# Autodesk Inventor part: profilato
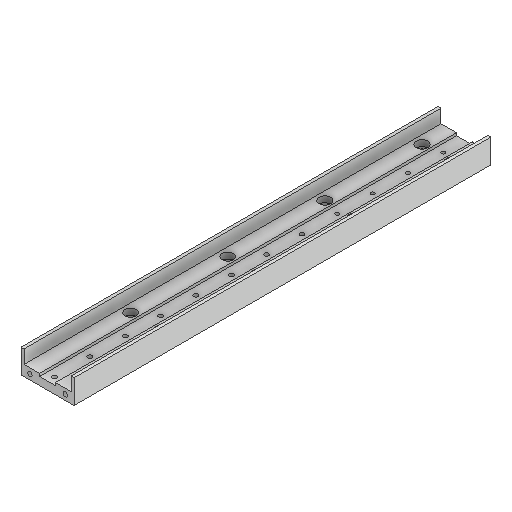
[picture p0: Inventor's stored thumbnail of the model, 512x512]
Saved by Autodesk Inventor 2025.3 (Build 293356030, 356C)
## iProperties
Created: 2025-11
Part Number: profilato
Material: Generico
Document SubType Name: Modeling
Designer: R5800u
Density: 1 g/cm^3
Appearance: Default
Author: R5800u
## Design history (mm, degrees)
feature "Base1"
sketch "Schizzo1"
  geometry: L1 (30, 0)-(30, -5.7) reference; L2 (30, 0)-(19.5, 0) reference; L3 (19.5, -1.2)-(19.5, 0) reference; L4 (10.5, -1.2)-(19.5, -1.2) reference; L5 (10.5, 0)-(10.5, -1.2) reference; L6 (0, 0)-(10.5, 0) reference; L7 (0, -5.7)-(0, 0) reference; L8 (30, -5.7)-(0, -5.7) reference; C1 r 1.45 at (5, -2.7) reference; C2 r 1.45 at (25, -2.7) reference; 1 further point
extrude "Estrusione1" cut sketch "Schizzo1" distance "d0" = 10; taper "d1" = 0 deg
sketch "Schizzo2"
  geometry: L1 (9.75, 2.6)-(3.25, 2.6) reference; L2 (0, 5.7)-(10.5, 5.7) reference; L3 (0, 5.7)-(0, 0) reference; L4 (0, 0)-(30, 0) reference; L5 (30, 0)-(30, 5.7) reference; L6 (19.5, 5.7)-(30, 5.7) reference; L7 (19.5, 5.7)-(19.5, 4.5) reference; L8 (19.5, 4.5)-(10.5, 4.5) reference; L9 (10.5, 4.5)-(10.5, 5.7) reference; C1 r 1.45 at (5, 3) reference; C2 r 1.45 at (25, 3) reference; 1 further point
extrude "Estrusione2" cut sketch "Schizzo2" stored distance "d2" = 10; taper "d3" = 0 deg
sketch "Schizzo3"
  geometry: L1 (19.5, 6)-(28.3, 6) reference; L2 (19.5, 4.5)-(19.5, 6) reference; L3 (10.5, 4.5)-(19.5, 4.5) reference; L4 (10.5, 6)-(10.5, 4.5) reference; L5 (1.7, 6)-(10.5, 6) reference; L6 (1.7, 13.6)-(1.7, 6) reference; L7 (1.7, 13.6)-(0, 13.6) reference; L8 (0, 0)-(0, 13.6) reference; L9 (30, 0)-(0, 0) reference; L10 (30, 0)-(30, 13.6) reference; L11 (30, 13.6)-(28.3, 13.6) reference; L12 (28.3, 6)-(28.3, 13.6) reference; C1 r 1.45 at (5, 3) reference; C2 r 1.45 at (25, 3) reference; 1 further point
extrude "Estrusione3" join sketch "Schizzo3" distance "d4" = 150; taper "d5" = 0 deg
sketch "Schizzo4"
  geometry: L1 (-4.5, -72)-(-4.5, -127); L2 (4, -70.5)-(4, -125.5); L3 (-13, -70.5)-(-13, -125.5); C1 r 1.7 at (4, -70.5) reference; C2 r 1.025 at (-4.5, -72) reference; C3 r 1.7 at (-13, -70.5) reference; C4 r 1.7 at (4, -15.5) reference; 4 further points
  constraints: 6 end point, 3 coincident, 3 vertical
  dimensions: "d6" = 55 distance of L2.start C4.centre (derived); "d7" = 55 distance of L1.start L1.end; "d8" = 55 distance of L2.start L2.end
hole "Foro1" sketch "Schizzo4" diameter "d9" = 2.4; stored, may be unused: countersink angle "d13" = 90 deg, drill point angle "d15" = 118 deg; dims "d10" = 6, "d11" = 4.4, "d12" = 2, "d14" = 8
hole "Foro2" sketch "Schizzo4" diameter "d16" = 3.242; stored, may be unused: countersink angle "d20" = 90 deg, drill point angle "d22" = 118 deg; dims "d17" = 8, "d18" = 6.3, "d19" = 3.4, "d21" = 8
pattern_linear "Serie rettangolare1" dims "d25" = 55
pattern_linear "Serie rettangolare2"
sketch "Schizzo5"
  geometry: C1 r 1.45 at (5, 3) reference; C2 r 1.45 at (25, 3) reference; 1 further point
hole "Foro3" sketch "Schizzo5" at (5, 3), (25, 3) diameter "d29" = 2.459; stored, may be unused: countersink angle "d33" = 90 deg, drill point angle "d35" = 118 deg; dims "d30" = 6, "d31" = 19.05, "d32" = 4.775, "d34" = 8.8
sketch "Schizzo8"
  geometry: L1 (4.5, -72)-(4.5, -92); C1 r 1.025 at (4.5, -72) reference; 2 further points
  constraints: 2 end point, 1 coincident, 1 vertical
  dimensions: "d50" = 20 distance of L1.start L1.end
hole "Foro6" sketch "Schizzo8" at (4.5, -92) diameter "d51" = 2.4; stored, may be unused: countersink angle "d55" = 90 deg, drill point angle "d57" = 118 deg; dims "d52" = 6, "d53" = 4, "d54" = 2, "d56" = 8
pattern_linear "Serie rettangolare3"
node "Solido1"
node "Linea chiusa proiettata1"
node "Linea chiusa proiettata2"
node "Linea chiusa proiettata3"
